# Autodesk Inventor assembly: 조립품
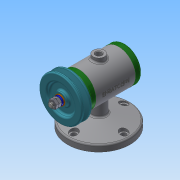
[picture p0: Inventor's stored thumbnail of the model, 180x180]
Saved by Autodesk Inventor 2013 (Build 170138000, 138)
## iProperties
Created: 2018-12
Part Number: 조립품
Document SubType Name: Assembly
Designer: Administrator
Author: Administrator
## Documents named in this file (14)
- C:\Users\Administrator\Desktop\481207V1043\조립품.iam
- C:\Users\Administrator\Desktop\481207V1043\본체.ipt
- C:\Users\Administrator\Desktop\481207V1043\축.ipt
- C:\Users\Administrator\Desktop\481207V1043\베어링 15 x 32 x 9.ipt
- C:\Users\Administrator\Desktop\481207V1043\뒤커버.ipt
- C:\Users\Administrator\Desktop\481207V1043\볼트 M4 x 12.ipt
- C:\Users\Administrator\Desktop\481207V1043\앞커버.ipt
- C:\Users\Administrator\Desktop\481207V1043\오일 실 15 25 7.ipt
- C:\Users\Administrator\Desktop\481207V1043\키 3 x 3 x 12.ipt
- C:\Users\Administrator\Desktop\481207V1043\V벨트풀리.ipt
- C:\Users\Administrator\Desktop\481207V1043\와셔 8x17.ipt
- C:\Users\Administrator\Desktop\481207V1043\스프링와셔 8.ipt
- C:\Users\Administrator\Desktop\481207V1043\너트 M8.ipt
- 너트 M8.ipt
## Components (1 placed, 1 different names)
1. V벨트풀리:1
